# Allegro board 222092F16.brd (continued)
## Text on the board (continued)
User.19: FIGURE | SIZE | 12.0 | 30.0 | 40.0 | 42.0 | 48.0 | 52.0 | 125.0 | 63.0x40.0 | DRILL CHART: TOP to BOTTOM | ALL UNITS ARE IN MILS | TOLERANCE | +2.0/-12.0 | +3.0/-3.0 | +2.0/-2.0 | PLATED | NON-PLATED | QTY | 259 | 6 | 5 | 8 | 64 | 3 | 4 | 2 | 1
